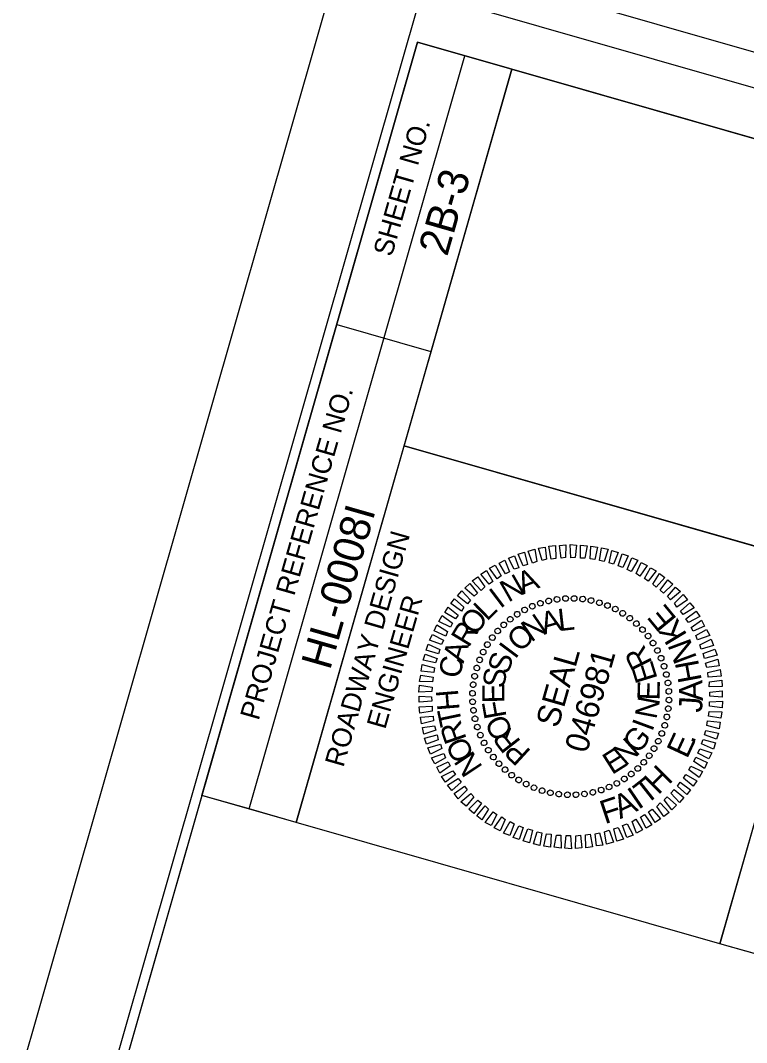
# Model space of a CAD drawing. Extents: x 2097440 to 2098186, y 685688 to 689676.
# Drawn here: x 2097729.8 to 2097803.9, y 689488.2 to 689592.6 of the extents above; entities that cross this region are included whole.
import ezdxf

# ---------------------------------------------------------------- set-up
doc = ezdxf.new("R2010")
doc.units = 0
for name, color, linetype in [('Sheet Data Field CELL', 7, 'Continuous'), ('Sheet Layout Plan Border', 7, 'Continuous'), ('Sheet PE Seal Cell', 7, 'Continuous'), ('Sheet Plot Border Inside CELL', 7, 'Continuous'), ('Sheet Plot Border Outside CELL', 7, 'Continuous'), ('Sheet Profile CELL', 7, 'Continuous'), ('Sheet Sticker Exception Certification CELL', 7, 'Continuous')]:
    doc.layers.add(name, color=color, linetype=linetype)

msp = doc.modelspace()

# ---------------------------------------------------------------- linework, layer by layer
at = {"layer": 'Sheet Layout Plan Border'}
msp.add_lwpolyline([(2097605.2, 689013.53), (2098008.99, 688897.94), (2098157.35, 689412.51), (2097846.92, 689501.38), (2097842.64, 689486.42), (2097810.24, 689495.7), (2097801.2, 689498.28), (2097757.94, 689510.67), (2097753.13, 689512.05), (2097748.3, 689513.43)], close=True, dxfattribs=at)
at = {"layer": 'Sheet PE Seal Cell'}
for p, q in [((2097783.71, 689533.3), (2097783.71, 689533.3)), ((2097784.57, 689533.47), (2097784.57, 689533.47)), ((2097785.43, 689533.55), (2097785.43, 689533.55)), ((2097786.31, 689533.55), (2097786.31, 689533.55)), ((2097787.2, 689533.47), (2097787.2, 689533.47)), ((2097788.06, 689533.34), (2097788.06, 689533.34)), ((2097788.91, 689533.12), (2097788.91, 689533.12)), ((2097781.25, 689532.38), (2097781.25, 689532.38)), ((2097782.05, 689532.78), (2097782.05, 689532.78)), ((2097782.86, 689533.06), (2097782.86, 689533.06)), ((2097789.74, 689532.82), (2097789.74, 689532.82)), ((2097790.52, 689532.45), (2097790.52, 689532.45)), ((2097791.28, 689532.05), (2097791.28, 689532.05)), ((2097779.79, 689531.43), (2097779.79, 689531.43)), ((2097780.5, 689531.95), (2097780.5, 689531.95)), ((2097792.01, 689531.55), (2097792.01, 689531.55)), ((2097778.51, 689530.23), (2097778.51, 689530.23)), ((2097779.11, 689530.87), (2097779.11, 689530.87)), ((2097792.68, 689530.98), (2097792.68, 689530.98)), ((2097793.32, 689530.38), (2097793.32, 689530.38)), ((2097777.94, 689529.56), (2097777.94, 689529.56)), ((2097793.88, 689529.7), (2097793.88, 689529.7)), ((2097794.4, 689528.99), (2097794.4, 689528.99)), ((2097777.04, 689528.07), (2097777.04, 689528.07)), ((2097777.44, 689528.83), (2097777.44, 689528.83)), ((2097794.83, 689528.24), (2097794.83, 689528.24)), ((2097776.67, 689527.28), (2097776.67, 689527.28)), ((2097795.23, 689527.44), (2097795.23, 689527.44)), ((2097776.37, 689526.45), (2097776.37, 689526.45)), ((2097795.52, 689526.63), (2097795.52, 689526.63)), ((2097795.75, 689525.77), (2097795.75, 689525.77)), ((2097776.02, 689524.74), (2097776.02, 689524.74)), ((2097776.14, 689525.6), (2097776.14, 689525.6)), ((2097795.92, 689524.91), (2097795.92, 689524.91)), ((2097775.94, 689523.85), (2097775.94, 689523.85)), ((2097796.01, 689524.06), (2097796.01, 689524.06)), ((2097775.93, 689522.98), (2097775.93, 689522.98)), ((2097785.97, 689523.52), (2097785.97, 689523.52)), ((2097796.01, 689523.18), (2097796.01, 689523.18)), ((2097776.02, 689522.12), (2097776.02, 689522.12)), ((2097795.92, 689522.29), (2097795.92, 689522.29)), ((2097776.19, 689521.26), (2097776.19, 689521.26)), ((2097795.57, 689520.58), (2097795.57, 689520.58)), ((2097795.8, 689521.43), (2097795.8, 689521.43)), ((2097776.43, 689520.41), (2097776.43, 689520.41)), ((2097776.71, 689519.59), (2097776.71, 689519.59)), ((2097795.27, 689519.75), (2097795.27, 689519.75)), ((2097777.11, 689518.8), (2097777.11, 689518.8)), ((2097794.9, 689518.96), (2097794.9, 689518.96)), ((2097777.54, 689518.05), (2097777.54, 689518.05)), ((2097794, 689517.48), (2097794, 689517.48)), ((2097794.5, 689518.21), (2097794.5, 689518.21)), ((2097778.06, 689517.34), (2097778.06, 689517.34)), ((2097778.62, 689516.66), (2097778.62, 689516.66)), ((2097793.43, 689516.81), (2097793.43, 689516.81)), ((2097779.26, 689516.06), (2097779.26, 689516.06)), ((2097779.93, 689515.49), (2097779.93, 689515.49)), ((2097792.15, 689515.61), (2097792.15, 689515.61)), ((2097792.83, 689516.17), (2097792.83, 689516.17)), ((2097780.66, 689514.99), (2097780.66, 689514.99)), ((2097781.42, 689514.59), (2097781.42, 689514.59)), ((2097790.69, 689514.66), (2097790.69, 689514.66)), ((2097791.44, 689515.09), (2097791.44, 689515.09)), ((2097782.21, 689514.22), (2097782.21, 689514.22)), ((2097783.03, 689513.92), (2097783.03, 689513.92)), ((2097783.89, 689513.69), (2097783.89, 689513.69)), ((2097784.75, 689513.57), (2097784.75, 689513.57)), ((2097785.64, 689513.48), (2097785.64, 689513.48)), ((2097786.51, 689513.48), (2097786.51, 689513.48)), ((2097787.37, 689513.57), (2097787.37, 689513.57)), ((2097788.23, 689513.74), (2097788.23, 689513.74)), ((2097789.08, 689513.97), (2097789.08, 689513.97)), ((2097789.89, 689514.26), (2097789.89, 689514.26))]:
    msp.add_line(p, q, dxfattribs=at)
for points in [[(2097782.05, 689537.16), (2097781.62, 689538.39), (2097782.3, 689538.59), (2097782.52, 689537.32)], [(2097783.04, 689537.42), (2097782.68, 689538.69), (2097783.35, 689538.77), (2097783.48, 689537.55)], [(2097783.98, 689537.57), (2097783.73, 689538.87), (2097784.42, 689538.94), (2097784.46, 689537.64)], [(2097784.98, 689537.66), (2097784.82, 689538.97), (2097785.48, 689539.01), (2097785.44, 689537.73)], [(2097785.99, 689537.7), (2097785.9, 689539.06), (2097786.57, 689538.99), (2097786.44, 689537.72)], [(2097786.98, 689537.67), (2097786.96, 689538.98), (2097787.65, 689538.91), (2097787.42, 689537.67)], [(2097787.96, 689537.58), (2097788.04, 689538.9), (2097788.71, 689538.77), (2097788.44, 689537.52)], [(2097788.91, 689537.43), (2097789.12, 689538.72), (2097789.78, 689538.57), (2097789.38, 689537.33)], [(2097789.88, 689537.17), (2097790.18, 689538.44), (2097790.83, 689538.25), (2097790.34, 689537.04)], [(2097779.32, 689536.05), (2097778.66, 689537.14), (2097779.25, 689537.47), (2097779.71, 689536.25)], [(2097780.21, 689536.53), (2097779.6, 689537.66), (2097780.23, 689537.91), (2097780.67, 689536.69)], [(2097781.12, 689536.89), (2097780.59, 689538.06), (2097781.25, 689538.27), (2097781.55, 689537.02)], [(2097790.83, 689536.88), (2097791.23, 689538.11), (2097791.85, 689537.89), (2097791.28, 689536.71)], [(2097791.73, 689536.52), (2097792.2, 689537.71), (2097792.83, 689537.45), (2097792.16, 689536.29)], [(2097777.65, 689534.99), (2097776.79, 689536.01), (2097777.36, 689536.39), (2097778.02, 689535.28)], [(2097778.45, 689535.55), (2097777.68, 689536.63), (2097778.27, 689536.96), (2097778.85, 689535.84)], [(2097792.67, 689536.08), (2097793.16, 689537.23), (2097793.78, 689536.91), (2097793.03, 689535.81)], [(2097793.52, 689535.57), (2097794.11, 689536.69), (2097794.71, 689536.37), (2097793.88, 689535.3)], [(2097776.84, 689534.37), (2097775.92, 689535.36), (2097776.47, 689535.75), (2097777.2, 689534.73)], [(2097794.36, 689535.01), (2097795.05, 689536.11), (2097795.57, 689535.69), (2097794.7, 689534.69)], [(2097795.09, 689534.39), (2097795.88, 689535.45), (2097796.39, 689534.99), (2097795.46, 689534.07)], [(2097775.42, 689533.01), (2097774.42, 689533.82), (2097774.86, 689534.33), (2097775.75, 689533.37)], [(2097776.11, 689533.77), (2097775.16, 689534.6), (2097775.66, 689535.08), (2097776.45, 689534.07)], [(2097795.87, 689533.75), (2097796.66, 689534.71), (2097797.18, 689534.25), (2097796.17, 689533.41)], [(2097774.8, 689532.25), (2097773.72, 689533.04), (2097774.1, 689533.51), (2097775.06, 689532.65)], [(2097796.56, 689533.05), (2097797.45, 689533.96), (2097797.88, 689533.42), (2097796.82, 689532.64)], [(2097797.17, 689532.25), (2097798.12, 689533.11), (2097798.57, 689532.58), (2097797.46, 689531.9)], [(2097774.21, 689531.48), (2097773.1, 689532.11), (2097773.46, 689532.65), (2097774.46, 689531.85)], [(2097797.73, 689531.47), (2097798.77, 689532.25), (2097799.15, 689531.69), (2097798, 689531.1)], [(2097773.69, 689530.63), (2097772.5, 689531.18), (2097772.84, 689531.79), (2097773.91, 689531.01)], [(2097798.27, 689530.59), (2097799.34, 689531.34), (2097799.64, 689530.73), (2097798.49, 689530.19)], [(2097773.2, 689529.71), (2097772.02, 689530.24), (2097772.3, 689530.84), (2097773.39, 689530.16)], [(2097798.76, 689529.76), (2097799.85, 689530.36), (2097800.18, 689529.77), (2097798.93, 689529.32)], [(2097772.78, 689528.83), (2097771.56, 689529.27), (2097771.85, 689529.87), (2097772.99, 689529.27)], [(2097799.14, 689528.82), (2097800.3, 689529.38), (2097800.55, 689528.75), (2097799.28, 689528.38)], [(2097772.17, 689526.97), (2097770.89, 689527.23), (2097771.09, 689527.86), (2097772.32, 689527.43)], [(2097772.45, 689527.89), (2097771.2, 689528.25), (2097771.4, 689528.87), (2097772.6, 689528.34)], [(2097799.51, 689527.92), (2097800.69, 689528.35), (2097800.91, 689527.75), (2097799.62, 689527.43)], [(2097799.74, 689526.94), (2097800.99, 689527.35), (2097801.12, 689526.67), (2097799.87, 689526.51)], [(2097771.99, 689525.98), (2097770.7, 689526.12), (2097770.81, 689526.8), (2097772.06, 689526.46)], [(2097799.97, 689525.98), (2097801.22, 689526.29), (2097801.32, 689525.62), (2097800.02, 689525.51)], [(2097771.84, 689525.03), (2097770.52, 689525.07), (2097770.65, 689525.72), (2097771.91, 689525.5)], [(2097800.13, 689525.02), (2097801.39, 689525.2), (2097801.45, 689524.56), (2097800.11, 689524.51)], [(2097771.79, 689524.04), (2097770.46, 689523.99), (2097770.51, 689524.68), (2097771.81, 689524.47)], [(2097800.17, 689523.99), (2097801.45, 689524.1), (2097801.45, 689523.46), (2097800.19, 689523.55)], [(2097771.77, 689523.05), (2097770.49, 689522.94), (2097770.49, 689523.58), (2097771.75, 689523.49)], [(2097800.15, 689522.99), (2097801.48, 689523.05), (2097801.43, 689522.36), (2097800.13, 689522.56)], [(2097771.81, 689522.02), (2097770.55, 689521.84), (2097770.49, 689522.48), (2097771.83, 689522.53)], [(2097800.1, 689522.01), (2097801.42, 689521.97), (2097801.3, 689521.32), (2097800.03, 689521.53)], [(2097771.97, 689521.06), (2097770.72, 689520.75), (2097770.62, 689521.42), (2097771.92, 689521.53)], [(2097799.95, 689521.06), (2097801.24, 689520.91), (2097801.13, 689520.24), (2097799.88, 689520.58)], [(2097772.2, 689520.1), (2097770.96, 689519.68), (2097770.82, 689520.37), (2097772.07, 689520.53)], [(2097772.44, 689519.11), (2097771.25, 689518.68), (2097771.03, 689519.29), (2097772.33, 689519.6)], [(2097799.77, 689520.07), (2097801.05, 689519.8), (2097800.85, 689519.18), (2097799.62, 689519.61)], [(2097772.8, 689518.22), (2097771.64, 689517.65), (2097771.39, 689518.29), (2097772.66, 689518.65)], [(2097799.49, 689519.15), (2097800.74, 689518.79), (2097800.54, 689518.16), (2097799.34, 689518.69)], [(2097773.18, 689517.28), (2097772.09, 689516.67), (2097771.76, 689517.27), (2097773.01, 689517.72)], [(2097799.16, 689518.2), (2097800.39, 689517.77), (2097800.09, 689517.17), (2097798.95, 689517.76)], [(2097773.67, 689516.45), (2097772.6, 689515.7), (2097772.3, 689516.3), (2097773.45, 689516.85)], [(2097798.25, 689516.41), (2097799.44, 689515.86), (2097799.1, 689515.25), (2097798.04, 689516.03)], [(2097798.74, 689517.33), (2097799.92, 689516.8), (2097799.64, 689516.19), (2097798.55, 689516.88)], [(2097774.21, 689515.57), (2097773.17, 689514.78), (2097772.79, 689515.35), (2097773.94, 689515.94)], [(2097797.73, 689515.55), (2097798.84, 689514.92), (2097798.48, 689514.38), (2097797.48, 689515.19)], [(2097774.77, 689514.78), (2097773.82, 689513.93), (2097773.37, 689514.46), (2097774.48, 689515.14)], [(2097775.38, 689513.99), (2097774.49, 689513.07), (2097774.06, 689513.61), (2097775.12, 689514.39)], [(2097797.14, 689514.79), (2097798.22, 689514), (2097797.84, 689513.53), (2097796.88, 689514.38)], [(2097776.07, 689513.29), (2097775.28, 689512.33), (2097774.76, 689512.79), (2097775.77, 689513.62)], [(2097795.83, 689513.27), (2097796.78, 689512.44), (2097796.29, 689511.95), (2097795.5, 689512.97)], [(2097796.53, 689514.03), (2097797.52, 689513.22), (2097797.08, 689512.7), (2097796.19, 689513.66)], [(2097776.85, 689512.65), (2097776.06, 689511.58), (2097775.55, 689512.04), (2097776.48, 689512.96)], [(2097777.58, 689512.02), (2097776.9, 689510.93), (2097776.37, 689511.35), (2097777.24, 689512.35)], [(2097795.1, 689512.67), (2097796.02, 689511.68), (2097795.47, 689511.29), (2097794.75, 689512.31)], [(2097778.42, 689511.47), (2097777.83, 689510.35), (2097777.24, 689510.67), (2097778.06, 689511.74)], [(2097779.27, 689510.96), (2097778.78, 689509.81), (2097778.16, 689510.13), (2097778.92, 689511.23)], [(2097793.49, 689511.48), (2097794.26, 689510.41), (2097793.67, 689510.08), (2097793.1, 689511.2)], [(2097794.29, 689512.04), (2097795.15, 689511.03), (2097794.58, 689510.65), (2097793.92, 689511.76)], [(2097780.21, 689510.52), (2097779.74, 689509.32), (2097779.11, 689509.59), (2097779.78, 689510.75)], [(2097781.11, 689510.16), (2097780.71, 689508.92), (2097780.09, 689509.14), (2097780.66, 689510.33)], [(2097790.82, 689510.15), (2097791.36, 689508.97), (2097790.69, 689508.77), (2097790.39, 689510.02)], [(2097791.73, 689510.51), (2097792.35, 689509.38), (2097791.71, 689509.12), (2097791.27, 689510.35)], [(2097792.62, 689510.99), (2097793.29, 689509.9), (2097792.69, 689509.57), (2097792.23, 689510.78)], [(2097782.06, 689509.87), (2097781.76, 689508.6), (2097781.11, 689508.79), (2097781.6, 689510)], [(2097783.03, 689509.61), (2097782.83, 689508.32), (2097782.16, 689508.47), (2097782.56, 689509.7)], [(2097783.99, 689509.46), (2097783.9, 689508.14), (2097783.23, 689508.26), (2097783.5, 689509.52)], [(2097784.96, 689509.37), (2097784.98, 689508.05), (2097784.29, 689508.13), (2097784.52, 689509.37)], [(2097785.95, 689509.34), (2097786.04, 689507.98), (2097785.37, 689508.05), (2097785.5, 689509.32)], [(2097786.96, 689509.38), (2097787.12, 689508.06), (2097786.47, 689508.02), (2097786.5, 689509.3)], [(2097787.96, 689509.47), (2097788.21, 689508.17), (2097787.53, 689508.09), (2097787.48, 689509.4)], [(2097788.9, 689509.62), (2097789.26, 689508.35), (2097788.59, 689508.27), (2097788.47, 689509.49)], [(2097789.89, 689509.87), (2097790.33, 689508.65), (2097789.64, 689508.45), (2097789.43, 689509.71)]]:
    msp.add_lwpolyline(points, close=True, dxfattribs=at)
for centre, major_axis in [((2097782.05, 689532.75), (-0.113, 0.265)), ((2097782.87, 689533.06), (-0.089, 0.274)), ((2097783.71, 689533.29), (-0.065, 0.281)), ((2097784.57, 689533.45), (-0.04, 0.285)), ((2097785.44, 689533.54), (-0.015, 0.288)), ((2097786.32, 689533.54), (0.01, 0.288)), ((2097787.19, 689533.48), (0.035, 0.286)), ((2097788.05, 689533.33), (0.06, 0.282)), ((2097788.9, 689533.11), (0.084, 0.275)), ((2097789.72, 689532.82), (0.108, 0.267)), ((2097780.5, 689531.93), (-0.157, 0.241)), ((2097781.26, 689532.37), (-0.135, 0.254)), ((2097790.52, 689532.46), (0.131, 0.257)), ((2097791.28, 689532.03), (0.153, 0.244)), ((2097779.13, 689530.85), (-0.197, 0.211)), ((2097779.79, 689531.42), (-0.177, 0.227)), ((2097792, 689531.53), (0.173, 0.23)), ((2097792.68, 689530.98), (0.193, 0.214)), ((2097778.51, 689530.23), (-0.214, 0.193)), ((2097793.3, 689530.36), (0.211, 0.197)), ((2097793.87, 689529.7), (0.227, 0.177)), ((2097777.46, 689528.83), (-0.244, 0.153)), ((2097777.96, 689529.55), (-0.23, 0.173)), ((2097794.38, 689528.99), (0.241, 0.157)), ((2097777.03, 689528.07), (-0.257, 0.131)), ((2097794.83, 689528.23), (0.254, 0.135)), ((2097776.67, 689527.27), (-0.267, 0.108)), ((2097795.2, 689527.44), (0.265, 0.113)), ((2097795.51, 689526.62), (0.274, 0.089)), ((2097776.16, 689525.6), (-0.282, 0.06)), ((2097776.38, 689526.45), (-0.275, 0.084)), ((2097795.74, 689525.78), (0.281, 0.065)), ((2097776.01, 689524.74), (-0.286, 0.035)), ((2097795.9, 689524.92), (0.285, 0.04)), ((2097775.94, 689523.86), (-0.288, 0.01)), ((2097795.99, 689524.05), (0.288, 0.015)), ((2097775.95, 689522.99), (-0.288, -0.015)), ((2097796, 689523.17), (0.288, -0.01)), ((2097776.04, 689522.12), (-0.285, -0.04)), ((2097795.78, 689521.44), (0.282, -0.06)), ((2097795.93, 689522.3), (0.286, -0.035)), ((2097776.2, 689521.26), (-0.281, -0.065)), ((2097776.43, 689520.41), (-0.274, -0.089)), ((2097795.57, 689520.59), (0.275, -0.084)), ((2097776.74, 689519.59), (-0.265, -0.113)), ((2097795.27, 689519.76), (0.267, -0.108)), ((2097777.12, 689518.8), (-0.254, -0.135)), ((2097794.48, 689518.21), (0.244, -0.153)), ((2097794.91, 689518.97), (0.257, -0.131)), ((2097777.56, 689518.05), (-0.241, -0.157)), ((2097778.07, 689517.34), (-0.227, -0.177)), ((2097793.99, 689517.48), (0.23, -0.173)), ((2097778.64, 689516.67), (-0.211, -0.197)), ((2097779.26, 689516.06), (-0.193, -0.214)), ((2097792.82, 689516.18), (0.197, -0.211)), ((2097793.43, 689516.81), (0.214, -0.193)), ((2097779.94, 689515.5), (-0.173, -0.23)), ((2097780.66, 689515.01), (-0.153, -0.244)), ((2097791.44, 689515.11), (0.157, -0.241)), ((2097792.15, 689515.62), (0.177, -0.227)), ((2097781.42, 689514.58), (-0.131, -0.257)), ((2097782.22, 689514.22), (-0.108, -0.267)), ((2097789.08, 689513.98), (0.089, -0.274)), ((2097789.89, 689514.29), (0.113, -0.265)), ((2097790.68, 689514.66), (0.135, -0.254)), ((2097783.04, 689513.92), (-0.084, -0.275)), ((2097783.89, 689513.7), (-0.06, -0.282)), ((2097784.75, 689513.56), (-0.035, -0.286)), ((2097785.63, 689513.49), (-0.01, -0.288)), ((2097786.5, 689513.5), (0.015, -0.288)), ((2097787.37, 689513.58), (0.04, -0.285)), ((2097788.23, 689513.74), (0.065, -0.281))]:
    msp.add_ellipse(centre, major_axis=major_axis, ratio=0.999708, dxfattribs=at)
at = {"layer": 'Sheet Plot Border Inside CELL'}
msp.add_lwpolyline([(2097993.01, 688838.44), (2098176.46, 689479.3), (2097770.72, 689595.44), (2097587.27, 688954.58)], close=True, dxfattribs=at)
at = {"layer": 'Sheet Plot Border Outside CELL'}
msp.add_lwpolyline([(2098000.68, 688832.6), (2098186.06, 689480.19), (2097763.05, 689601.28), (2097577.67, 688953.69)], close=True, dxfattribs=at)
at = {"layer": 'Sheet Profile CELL'}
for p, q in [((2097753.13, 689512.05), (2097775.15, 689588.98)), ((2097762.09, 689561.51), (2097771.7, 689558.76)), ((2097768.95, 689549.14), (2097812.19, 689536.77))]:
    msp.add_line(p, q, dxfattribs=at)
for points in [[(2097770.33, 689590.36), (2097605.2, 689013.53), (2098008.99, 688897.94), (2098174.11, 689474.77)], [(2097748.3, 689513.43), (2097770.33, 689590.36), (2097779.96, 689587.6), (2097757.94, 689510.67)], [(2097768.95, 689549.14), (2097779.96, 689587.6), (2097823.22, 689575.22), (2097812.21, 689536.76)], [(2097757.94, 689510.67), (2097768.95, 689549.14), (2097812.21, 689536.76), (2097801.2, 689498.28)]]:
    msp.add_lwpolyline(points, close=True, dxfattribs=at)
at = {"layer": 'Sheet Sticker Exception Certification CELL'}
for p, q in [((2097801.2, 689498.28), (2097823.22, 689575.21)), ((2097810.24, 689495.7), (2097801.2, 689498.28))]:
    msp.add_line(p, q, dxfattribs=at)

# ---------------------------------------------------------------- texts
at = {"layer": 'Sheet Data Field CELL'}
for s, p in [('2B-3', (2097773.35, 689568.4)), ('HL-0008I', (2097761.38, 689526.14))]:
    msp.add_text(s, height=3.1, rotation=74.0259, dxfattribs=at).set_placement(p)
at = {"layer": 'Sheet PE Seal Cell'}
for s, height, rotation, p in [('A', 2.26, 22.643, (2097781.06, 689533.91)), ('N', 2.26, 29.8448, (2097779.6, 689533.1)), ('I', 2.26, 37.046, (2097778.77, 689532.45)), ('L', 2.26, 44.2468, (2097777.4, 689531.15)), ('O', 2.26, 51.4471, (2097776.2, 689529.66)), ('A', 2.26, 15.7862, (2097783.24, 689529.83)), ('L', 2.26, 6.4267, (2097784.78, 689530.2)), ('E', 2.4, 129.5189, (2097796.89, 689531.46)), ('R', 2.26, 58.647, (2097775.55, 689528.46)), ('N', 2.26, 34.5025, (2097781.93, 689529.02)), ('K', 2.4, 121.235, (2097797.92, 689529.8)), ('O', 2.26, 43.8594, (2097780.79, 689527.96)), ('I', 2.26, 53.2155, (2097780.3, 689527.26)), ('N', 2.4, 110.5092, (2097798.89, 689527.47)), ('A', 2.26, 73.0462, (2097775.01, 689526.86)), ('S', 2.26, 71.9263, (2097779.56, 689525.69)), ('SEAL', 2.399, 74.0259, (2097784.68, 689520.23)), ('046981', 2.399, 74.0259, (2097787.62, 689517.65)), ('R', 2.26, 116.5073, (2097794.35, 689526.99)), ('C', 2.26, 80.2458, (2097774.69, 689525.31)), ('E', 2.26, 107.15, (2097794.86, 689525.36)), ('H', 2.4, 100.5252, (2097799.37, 689525.17)), ('S', 2.26, 81.2815, (2097779.18, 689524.3)), ('E', 2.26, 90.637, (2097779.21, 689522.85)), ('E', 2.26, 88.4377, (2097795.03, 689523.11)), ('A', 2.4, 91.6849, (2097799.47, 689523.09)), ('H', 2.26, 94.6454, (2097774.62, 689522.17)), ('F', 2.26, 99.9929, (2097779.43, 689521.46)), ('N', 2.26, 79.0823, (2097794.71, 689521.14)), ('J', 2.4, 86.427, (2097799.37, 689521.85)), ('T', 2.26, 101.8457, (2097774.9, 689520.74)), ('R', 2.26, 109.0464, (2097775.37, 689519.19)), ('O', 2.26, 118.7071, (2097780.2, 689519.86)), ('I', 2.26, 69.7271, (2097794.29, 689519.87)), ('R', 2.26, 128.0655, (2097780.95, 689518.92)), ('G', 2.26, 51.0161, (2097792.84, 689517.56)), ('E', 2.4, 65.0836, (2097797.85, 689517.09)), ('O', 2.26, 116.2476, (2097776.18, 689517.52)), ('N', 2.26, 41.6598, (2097791.55, 689516.35)), ('.', 2.4, 72.1929, (2097798.55, 689518.61)), ('N', 2.26, 123.4494, (2097777.04, 689516.32)), ('P', 2.26, 137.4248, (2097782.01, 689517.95)), ('E', 2.26, 32.3028, (2097790.18, 689515.49)), ('H', 2.4, 44.8992, (2097794.9, 689513.39)), ('T', 2.4, 38.099, (2097793.64, 689512.4)), ('F', 2.4, 18.4401, (2097789.45, 689510.47)), ('A', 2.4, 25.4567, (2097791.02, 689510.99)), ('I', 2.4, 34.297, (2097792.88, 689511.92))]:
    msp.add_text(s, height=height, rotation=rotation, dxfattribs=at).set_placement(p)
at = {"layer": 'Sheet Profile CELL'}
for s, p in [('SHEET NO.', (2097767.69, 689568.36)), ('PROJECT REFERENCE NO.', (2097754.09, 689521.01)), ('ROADWAY DESIGN', (2097762.75, 689516.22)), ('ENGINEER', (2097767.02, 689520.1))]:
    msp.add_text(s, height=2, rotation=74.0259, dxfattribs=at).set_placement(p)

doc.saveas('drawing.dxf')
